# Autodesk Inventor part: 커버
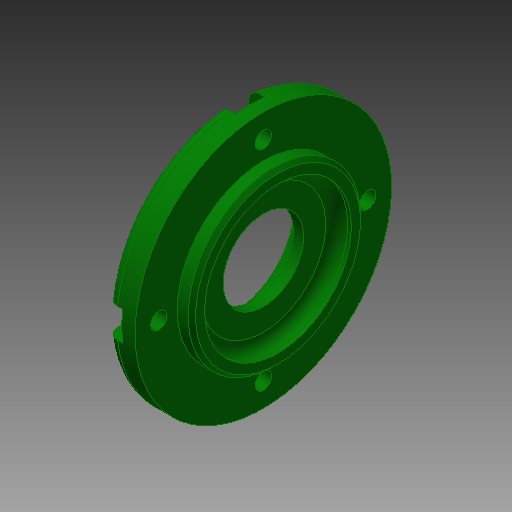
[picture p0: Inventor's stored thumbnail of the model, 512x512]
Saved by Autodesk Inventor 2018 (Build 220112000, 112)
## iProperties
Created: 2020-05
Part Number: 커버
Material: 알루미늄 6061
Document SubType Name: Modeling
Designer: mduedu
Density: 1 g/cm^3
Appearance: 진녹색
Author: mduedu
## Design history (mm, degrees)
sketch "스케치1"
  geometry: L1 (0, 0)-(8, 0); L2 (8, 0)-(8, 35); L3 (8, 35)-(0, 35); L4 (0, 35)-(0, 0); L5 (8, 0)-(12, 0); L6 (12, 0)-(12, 23.5); L7 (12, 23.5)-(8, 23.5); L8 (8, 23.5)-(8, 0)
  constraints: 16 end point, 4 parallel, 2 horizontal, 2 perpendicular
  dimensions: "d0" = 70 diameter of L3 L1; "d2" = 47 diameter of L7 L5; "d3" = 4 distance of L6.end L7.end; "d4" = 12 distance between parallel lines of L4 L6
revolve "회전1" sketch "스케치1" stored, may be unused: angle "d5" = 90 deg
hole "구멍1" diameter "d8" = 22; stored, may be unused: countersink angle "d12" = 90 deg, drill point angle "d14" = 118 deg; dims "d6" = 10, "d7" = 10, "d9" = 6, "d10" = 32, "d11" = 5.2, "d13" = 8
hole "구멍2" diameter "d17" = 40; stored, may be unused: countersink angle "d21" = 90 deg, drill point angle "d23" = 0 deg; dims "d15" = 10, "d16" = 10, "d18" = 6, "d19" = 32, "d20" = 5.2, "d22" = 4
fillet "모깎기1" dims "d24" = 3
fillet "모깎기2" dims "d25" = 3
fillet "모깎기3" dims "d26" = 0.3
chamfer "모따기1" distance "d27" = 0.5; stored, may be unused: second distance "d28" = 2, angle "d29" = 30 deg
chamfer "모따기2" distance "d30" = 1; stored, may be unused: second distance "d31" = 2, angle "d32" = 30 deg
sketch "스케치2" dims "d33" = 57
  geometry: L1 (-4, 28.5)-(4, 28.5); L2 (4, 28.5)-(4, 38.5); L3 (4, 38.5)-(-4, 38.5); L4 (-4, 38.5)-(-4, 28.5); 4 further points
  constraints: 8 end point, 2 horizontal alignment, 2 midpoint, 2 parallel, 2 vertical alignment, 1 coincident, 1 horizontal, 1 perpendicular, 6 other
  dimensions: "d34" = 8 distance between parallel lines of L2 L4; "d35" = 10 distance of point (0, 28.5) point (0, 38.5)
extrude "돌출1" cut sketch "스케치2" distance "d36" = 4.4; taper "d37" = 0 deg
sketch "스케치3"
  geometry: A1 r 4 centre (0, 28.5) between (-4, 28.5) and (4, 28.5) reference; 2 further points
  constraints: 1 coincident
hole "구멍3" sketch "스케치3" at (0, 28.5) diameter "d38" = 4.5; stored, may be unused: countersink angle "d42" = 90 deg, drill point angle "d44" = 0 deg; dims "d39" = 6, "d40" = 32, "d41" = 5.2, "d43" = 4
node "솔리드1"
pattern_circular "원형 패턴1" dims angle "d46" = 360 deg
